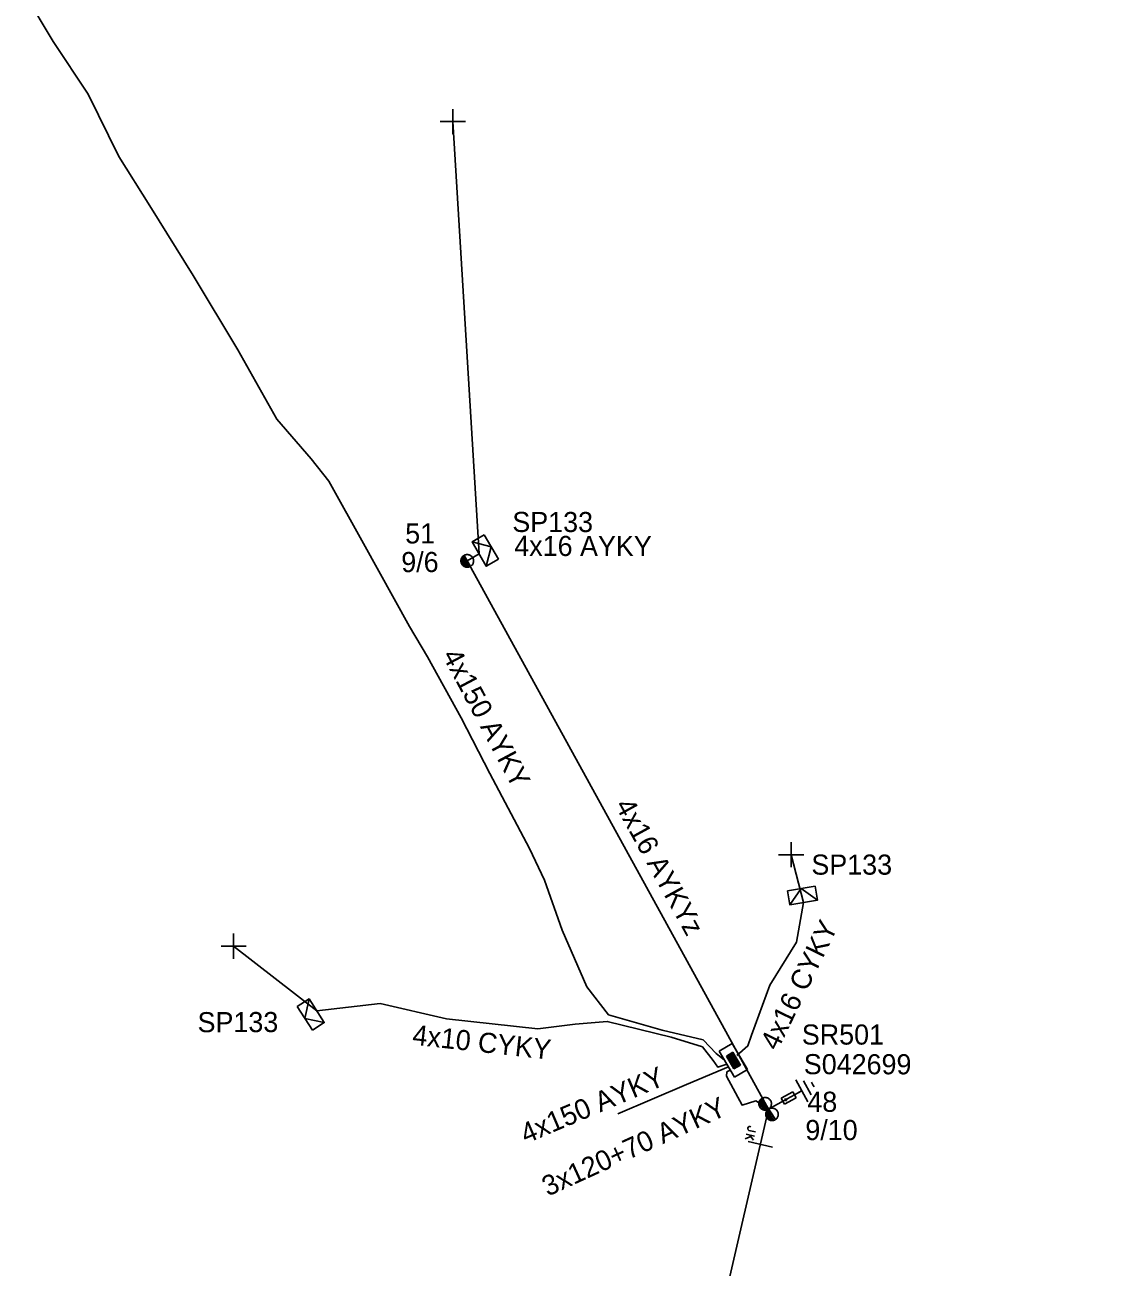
# Model space of a CAD drawing. Extents: x -748492 to -735633, y -1146251 to -1139940.
# Drawn here: x -743226 to -743171.6, y -1140437.7 to -1140375.9 of the extents above; entities that cross this region are included whole.
import ezdxf

# ---------------------------------------------------------------- set-up
doc = ezdxf.new("R2010")
doc.units = 0
for name, color, linetype in [('Vrstva 1', 7, 'Continuous'), ('Vrstva 12', 7, 'Continuous'), ('Vrstva 13', 7, 'Continuous'), ('Vrstva 14', 7, 'Continuous'), ('Vrstva 15', 7, 'Continuous'), ('Vrstva 16', 7, 'Continuous'), ('Vrstva 18', 7, 'Continuous'), ('Vrstva 2', 7, 'Continuous'), ('Vrstva 28', 7, 'Continuous'), ('Vrstva 29', 7, 'Continuous'), ('Vrstva 30', 7, 'Continuous'), ('Vrstva 31', 7, 'Continuous'), ('Vrstva 33', 7, 'Continuous'), ('Vrstva 34', 7, 'Continuous'), ('Vrstva 5', 7, 'Continuous'), ('Vrstva 52', 7, 'Continuous'), ('Vrstva 54', 7, 'Continuous'), ('Vrstva 55', 7, 'Continuous'), ('Vrstva 59', 7, 'Continuous'), ('Vrstva 6', 7, 'Continuous'), ('Vrstva 8', 7, 'Continuous'), ('Vrstva 9', 7, 'Continuous')]:
    doc.layers.add(name, color=color, linetype=linetype)

# ---------------------------------------------------------------- blocks, each defined once
blk = doc.blocks.new('NN440')
at = {"layer": 'Vrstva 2'}
for points in [[(0.63, 0), (0.63, 0.06), (0.62, 0.13), (0.6, 0.19), (0.58, 0.25), (0.55, 0.31), (0.51, 0.37), (0.47, 0.42), (0.42, 0.46), (0.37, 0.51), (0.32, 0.54), (0.26, 0.57), (0.2, 0.59), (0.13, 0.61), (0.07, 0.62), (0, 0.63), (-0.06, 0.62), (-0.13, 0.61), (-0.19, 0.59), (-0.26, 0.57), (-0.31, 0.54), (-0.37, 0.51), (-0.42, 0.46), (-0.47, 0.42), (-0.51, 0.37), (-0.54, 0.31), (-0.57, 0.25), (-0.6, 0.19), (-0.62, 0.13), (-0.63, 0.06), (-0.63, 0), (-0.63, -0.07), (-0.62, -0.14), (-0.6, -0.2), (-0.57, -0.26), (-0.54, -0.32), (-0.51, -0.37), (-0.47, -0.43), (-0.42, -0.47), (-0.37, -0.51), (-0.31, -0.55), (-0.26, -0.58), (-0.19, -0.6), (-0.13, -0.62), (-0.06, -0.63), (0, -0.63), (0.07, -0.63), (0.13, -0.62), (0.2, -0.6), (0.26, -0.58), (0.32, -0.55), (0.37, -0.51), (0.42, -0.47), (0.47, -0.43), (0.51, -0.37), (0.55, -0.32), (0.58, -0.26), (0.6, -0.2), (0.62, -0.14), (0.63, -0.07), (0.63, 0)], [(-0.63, 0), (0.63, 0)], [(-0.6, -0.18), (0.57, -0.18)], [(-0.51, -0.32), (0.5, -0.32)], [(-0.37, -0.47), (0.35, -0.47)]]:
    blk.add_lwpolyline(points, dxfattribs=at)
blk = doc.blocks.new('NN450')
at = {"layer": 'Vrstva 2'}
for points in [[(0, 0), (0, 0.07), (-0.01, 0.13), (-0.03, 0.19), (-0.05, 0.25), (-0.08, 0.31), (-0.12, 0.37), (-0.16, 0.42), (-0.21, 0.46), (-0.26, 0.51), (-0.31, 0.54), (-0.37, 0.57), (-0.43, 0.59), (-0.5, 0.61), (-0.56, 0.62), (-0.63, 0.62), (-0.69, 0.62), (-0.75, 0.61), (-0.82, 0.59), (-0.88, 0.57), (-0.94, 0.54), (-0.99, 0.51), (-1.04, 0.46), (-1.09, 0.42), (-1.13, 0.37), (-1.17, 0.31), (-1.2, 0.25), (-1.22, 0.19), (-1.24, 0.13), (-1.25, 0.07), (-1.25, 0), (-1.25, -0.07), (-1.24, -0.13), (-1.22, -0.19), (-1.2, -0.25), (-1.17, -0.31), (-1.13, -0.37), (-1.09, -0.42), (-1.04, -0.46), (-0.99, -0.51), (-0.94, -0.54), (-0.88, -0.57), (-0.82, -0.59), (-0.75, -0.61), (-0.69, -0.62), (-0.62, -0.63), (-0.56, -0.62), (-0.5, -0.61), (-0.43, -0.59), (-0.37, -0.57), (-0.31, -0.54), (-0.26, -0.51), (-0.21, -0.46), (-0.16, -0.42), (-0.12, -0.37), (-0.08, -0.31), (-0.05, -0.25), (-0.03, -0.19), (-0.01, -0.13), (0, -0.07), (0, 0)], [(1.25, 0), (1.25, 0.07), (1.24, 0.13), (1.22, 0.19), (1.2, 0.25), (1.17, 0.31), (1.13, 0.37), (1.09, 0.42), (1.04, 0.46), (0.99, 0.51), (0.94, 0.54), (0.88, 0.57), (0.82, 0.59), (0.75, 0.61), (0.69, 0.62), (0.62, 0.62), (0.56, 0.62), (0.5, 0.61), (0.43, 0.59), (0.37, 0.57), (0.31, 0.54), (0.26, 0.51), (0.21, 0.46), (0.16, 0.42), (0.12, 0.37), (0.08, 0.31), (0.05, 0.25), (0.03, 0.19), (0.01, 0.13), (0, 0.07), (0, 0), (0, -0.07), (0.01, -0.13), (0.03, -0.19), (0.05, -0.25), (0.08, -0.31), (0.12, -0.37), (0.16, -0.42), (0.21, -0.46), (0.26, -0.51), (0.31, -0.54), (0.37, -0.57), (0.43, -0.59), (0.5, -0.61), (0.56, -0.62), (0.63, -0.63), (0.69, -0.62), (0.75, -0.61), (0.82, -0.59), (0.88, -0.57), (0.94, -0.54), (0.99, -0.51), (1.04, -0.46), (1.09, -0.42), (1.13, -0.37), (1.17, -0.31), (1.2, -0.25), (1.22, -0.19), (1.24, -0.13), (1.25, -0.07), (1.25, 0)], [(-1.25, 0), (1.25, 0)], [(-1.23, -0.16), (-0.02, -0.16)], [(-1.16, -0.32), (-0.09, -0.32)], [(-1.03, -0.47), (-0.22, -0.47)], [(0.02, -0.16), (1.23, -0.16)], [(0.09, -0.32), (1.16, -0.32)], [(0.22, -0.47), (1.03, -0.47)]]:
    blk.add_lwpolyline(points, dxfattribs=at)
blk = doc.blocks.new('NN840')
at = {"layer": 'Vrstva 15'}
for points in [[(0.003, 0.619), (0.003, -0.631)], [(-0.538, -0.385), (-0.538, -0.71)], [(-0.332, -0.385), (-0.332, -0.798)], [(-0.332, -0.641), (-0.125, -0.385)], [(-0.263, -0.557), (-0.091, -0.798)], [(-0.745, -0.71), (-0.745, -0.66)], [(-0.73, -0.764), (-0.745, -0.71)], [(-0.657, -0.798), (-0.73, -0.764)], [(-0.627, -0.798), (-0.657, -0.798)], [(-0.558, -0.764), (-0.627, -0.798)], [(-0.538, -0.71), (-0.558, -0.764)]]:
    blk.add_lwpolyline(points, dxfattribs=at)
blk = doc.blocks.new('NN800')
at = {"layer": 'Vrstva 1'}
for points in [[(-0.442, 0.442), (0.442, -0.442)], [(-0.442, -0.442), (0.442, 0.442)]]:
    blk.add_lwpolyline(points, dxfattribs=at)
blk = doc.blocks.new('NN820')
at = {"layer": 'Vrstva 13'}
for points in [[(-0.003, 0.004), (-0.003, -1.049)], [(-0.165, -0.813), (0.165, -0.813)], [(-0.165, -1.473), (-0.165, -0.813)], [(-0.003, -1.049), (-0.062, -0.926)], [(-0.003, -1.049), (0.057, -0.926)], [(0.165, -0.813), (0.165, -1.473)], [(0.165, -1.473), (-0.165, -1.473)], [(-0.003, -1.473), (-0.003, -1.871)]]:
    blk.add_lwpolyline(points, dxfattribs=at)
blk = doc.blocks.new('NN620')
at = {"layer": 'Vrstva 8'}
for points in [[(0.752, 0.004), (-0.748, 0.004)], [(-0.748, 0.004), (-0.748, -0.746)], [(0.752, -0.746), (0.752, 0.004)], [(0.368, -0.18), (-0.376, -0.18)], [(-0.376, -0.18), (-0.376, -0.558)], [(-0.376, -0.558), (0.368, -0.558)], [(0.321, -0.227), (-0.329, -0.227)], [(-0.329, -0.227), (-0.329, -0.51)], [(-0.329, -0.51), (0.321, -0.51)], [(0.274, -0.274), (-0.281, -0.274)], [(-0.281, -0.274), (-0.281, -0.463)], [(-0.281, -0.463), (0.274, -0.463)], [(0.227, -0.321), (-0.234, -0.321)], [(-0.234, -0.321), (-0.234, -0.416)], [(-0.234, -0.416), (0.227, -0.416)], [(-0.193, -0.369), (0.185, -0.369)], [(0.227, -0.416), (0.227, -0.321)], [(0.274, -0.463), (0.274, -0.274)], [(0.321, -0.51), (0.321, -0.227)], [(0.368, -0.558), (0.368, -0.18)], [(-0.748, -0.746), (0.752, -0.746)]]:
    blk.add_lwpolyline(points, dxfattribs=at)
blk = doc.blocks.new('NN630')
at = {"layer": 'Vrstva 9'}
for points in [[(-0.003, -0.7), (-0.703, 0)], [(-0.703, -0.7), (-0.703, 0), (0.697, 0), (0.697, -0.7)], [(-0.003, -0.7), (0.697, 0)], [(-0.703, -0.7), (0.697, -0.7)]]:
    blk.add_lwpolyline(points, dxfattribs=at)
blk = doc.blocks.new('NN810')
at = {"layer": 'Vrstva 14'}
for points in [[(0.004, -0.64), (0.004, -1.89)], [(0.629, -1.89), (-0.621, -1.89)], [(0.388, -2.2), (-0.399, -2.2)], [(0.004, -2.515), (-0.124, -2.515)], [(0.137, -2.515), (0.004, -2.515)]]:
    blk.add_lwpolyline(points, dxfattribs=at)

msp = doc.modelspace()

# ---------------------------------------------------------------- linework, layer by layer
at = {"layer": 'Vrstva 1'}
msp.add_lwpolyline([(-743171.59, -1140548.26), (-743193.75, -1140527.99), (-743201.28, -1140486.88), (-743194.481, -1140453.61), (-743188.98, -1140429.87)], dxfattribs=at)
at = {"layer": 'Vrstva 5'}
for points in [[(-743191.168, -1140427.439), (-743191.58, -1140427.1), (-743192.24, -1140426.43), (-743194.28, -1140425.94), (-743196.94, -1140425.18), (-743198.02, -1140423.79), (-743199.25, -1140420.97), (-743200.13, -1140418.48), (-743200.88, -1140416.91), (-743202.84, -1140413.18), (-743204.28, -1140410.41), (-743205.95, -1140407.37), (-743206.84, -1140405.86), (-743209.13, -1140401.73), (-743210.85, -1140398.63), (-743211.74, -1140397.52), (-743213.44, -1140395.55), (-743215.38, -1140392.11), (-743217.6, -1140388.4), (-743219.76, -1140384.94), (-743221.3, -1140382.48), (-743222.83, -1140379.39), (-743224.57, -1140376.77), (-743225.98, -1140374.39)], [(-743190.976, -1140427.766), (-743193.063, -1140428.649), (-743196.485, -1140430.1)], [(-743190.855, -1140427.913), (-743191.063, -1140428.019), (-743191.07, -1140428.23), (-743190.3, -1140429.67), (-743189.62, -1140429.46), (-743188.98, -1140429.87)]]:
    msp.add_lwpolyline(points, dxfattribs=at)
at = {"layer": 'Vrstva 52'}
for points in [[(-743203.97, -1140402.6), (-743203.38, -1140402.257)], [(-743190.553, -1140427.201), (-743190.02, -1140426.73), (-743189.826, -1140426.197), (-743188.92, -1140423.71), (-743187.59, -1140421.57), (-743187.24, -1140419.59)], [(-743191.05, -1140427.64), (-743191.51, -1140427.78), (-743191.74, -1140427.45), (-743192.27, -1140426.78), (-743193.83, -1140426.3), (-743197.01, -1140425.51), (-743198.61, -1140425.64), (-743200.46, -1140425.88), (-743205, -1140425.38), (-743208.3, -1140424.62), (-743211.46, -1140424.98)]]:
    msp.add_lwpolyline(points, dxfattribs=at)
at = {"layer": 'Vrstva 54'}
msp.add_lwpolyline([(-743188.98, -1140429.87), (-743203.97, -1140402.6)], dxfattribs=at)
at = {"layer": 'Vrstva 59'}
for points in [[(-743203.38, -1140402.257), (-743204.69, -1140380.75)], [(-743187.24, -1140419.59), (-743187.858, -1140417.218)], [(-743211.46, -1140424.98), (-743215.596, -1140421.764)]]:
    msp.add_lwpolyline(points, dxfattribs=at)

# ---------------------------------------------------------------- block references
at = {"layer": 'Vrstva 13', "xscale": 0.5, "yscale": 0.5}
for name, p, rotation in [('NN440', (-743203.97, -1140402.6), -60.11895286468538), ('NN450', (-743188.98, -1140429.87), -57.070359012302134)]:
    msp.add_blockref(name, p, dxfattribs=dict(at, rotation=rotation))
at = {"layer": 'Vrstva 15', "rotation": 118.7962772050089}
msp.add_blockref('NN810', (-743188.98, -1140429.87), dxfattribs=at)
at = {"layer": 'Vrstva 16', "rotation": 118.89766439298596}
msp.add_blockref('NN820', (-743188.98, -1140429.87), dxfattribs=at)
at = {"layer": 'Vrstva 18', "rotation": -103.04396104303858}
msp.add_blockref('NN840', (-743189.385, -1140431.62), dxfattribs=at)
at = {"layer": 'Vrstva 28', "rotation": 120.46554220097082}
msp.add_blockref('NN620', (-743191.05, -1140427.64), dxfattribs=at)
at = {"layer": 'Vrstva 31'}
for p, rotation in [((-743203.38, -1140402.257), 120.14531605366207), ((-743187.24, -1140419.59), -170.57048972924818), ((-743211.46, -1140424.98), -57.264762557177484)]:
    msp.add_blockref('NN630', p, dxfattribs=dict(at, rotation=rotation))
at = {"layer": 'Vrstva 34'}
for p, rotation in [((-743204.69, -1140380.75), 44.99999995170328), ((-743187.858, -1140417.218), 45), ((-743215.596, -1140421.764), 45)]:
    msp.add_blockref('NN800', p, dxfattribs=dict(at, rotation=rotation))

# ---------------------------------------------------------------- texts
at = {"layer": 'Vrstva 12'}
for s, rotation, p in [('9/6', 0.142, (-743207.253, -1140403.16)), ('9/10', 359.966, (-743187.152, -1140431.41))]:
    msp.add_text(s, height=1, rotation=rotation, dxfattribs=at).set_placement(p)
at = {"layer": 'Vrstva 14'}
for s, rotation, p in [('51', 0.084, (-743207.057, -1140401.735)), ('48', 0.227, (-743187.051, -1140430.01))]:
    msp.add_text(s, height=1, rotation=rotation, dxfattribs=at).set_placement(p)
at = {"layer": 'Vrstva 29'}
msp.add_text('S042699', height=1, rotation=359.913, dxfattribs=at).set_placement((-743187.229, -1140428.134))
at = {"layer": 'Vrstva 30'}
msp.add_text('SR501', height=1, rotation=359.991, dxfattribs=at).set_placement((-743187.327, -1140426.661))
at = {"layer": 'Vrstva 33'}
for rotation, p in [(359.948, (-743201.729, -1140401.164)), (0.119, (-743217.387, -1140426.047))]:
    msp.add_text('SP133', height=1, rotation=rotation, dxfattribs=at).set_placement(p)
msp.add_text('SP133', height=1, dxfattribs=at).set_placement((-743186.851, -1140418.209))
at = {"layer": 'Vrstva 54'}
for s, rotation, p in [('4x16 AYKY', 359.878, (-743201.632, -1140402.352)), ('4x16 CYKY', 64.018, (-743188.538, -1140427.015)), ('4x10 CYKY', 353.715, (-743206.735, -1140426.658))]:
    msp.add_text(s, height=1, rotation=rotation, dxfattribs=at).set_placement(p)
at = {"layer": 'Vrstva 55'}
msp.add_text('4x16 AYKYz', height=1, rotation=298.796, dxfattribs=at).set_placement((-743196.646, -1140414.757))
at = {"layer": 'Vrstva 6'}
for s, rotation, p in [('4x150 AYKY', 298.054, (-743205.241, -1140407.3)), ('4x150 AYKY', 22.979, (-743201.057, -1140431.607)), ('3x120+70 AYKY', 24.537, (-743199.964, -1140434.229))]:
    msp.add_text(s, height=1, rotation=rotation, dxfattribs=at).set_placement(p)

doc.saveas('drawing.dxf')
